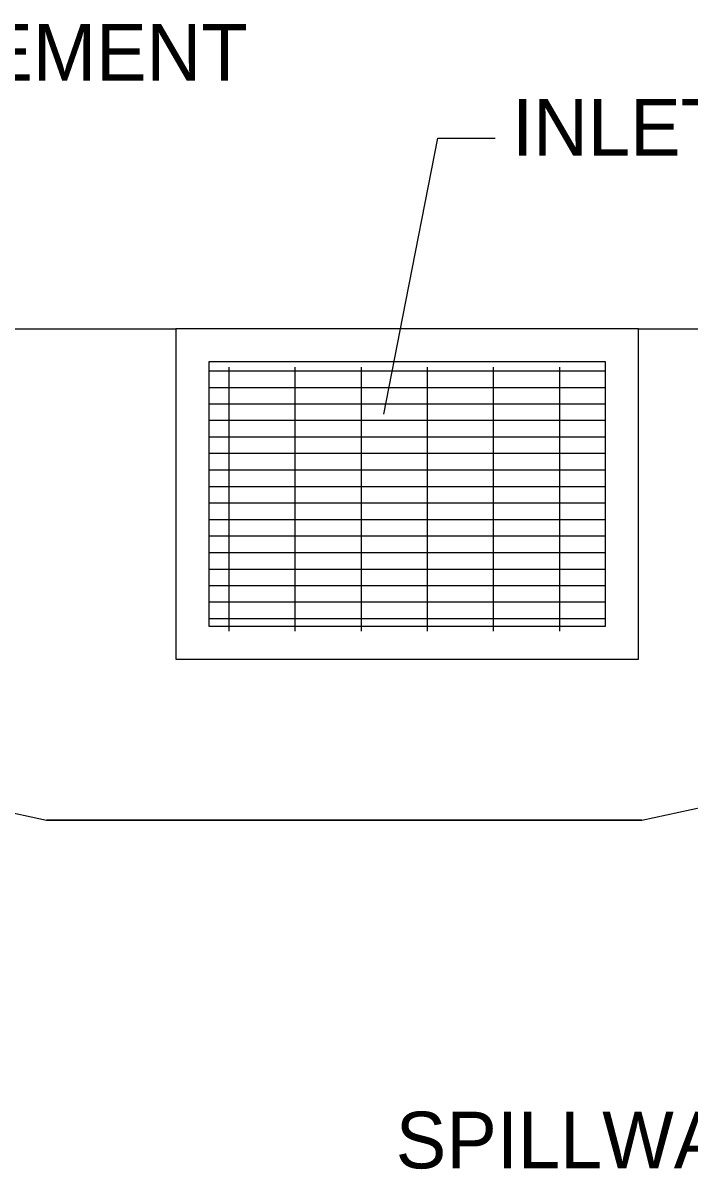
# Model space of a CAD drawing. Extents: x 6707406 to 6714471, y 1868570 to 1872341.
# Drawn here: x 6714138.1 to 6714208.7, y 1870045.9 to 1870168.4 of the extents above; entities that cross this region are included whole.
import ezdxf

# ---------------------------------------------------------------- set-up
doc = ezdxf.new("R2010")
doc.units = 0
doc.layers.add('Control (1)', color=7, linetype='Continuous')
doc.layers.add('Nongeo Data(60)', color=7, linetype='Continuous')

# ---------------------------------------------------------------- blocks, each defined once
blk = doc.blocks.new('SC30')
at = {"layer": 'Control (1)'}
for p, q in [((0.198117, 0.180633), (0.198117, 0.20095)), ((0.2032, 0.180633), (0.2032, 0.20095)), ((0.208283, 0.180633), (0.208283, 0.20095)), ((0.213367, 0.180633), (0.213367, 0.20095)), ((0.218433, 0.180633), (0.218433, 0.20095)), ((0.223517, 0.180633), (0.223517, 0.20095)), ((0.19655, 0.200667), (0.227033, 0.200667)), ((0.19655, 0.199383), (0.227033, 0.199383)), ((0.19655, 0.198117), (0.227033, 0.198117)), ((0.19655, 0.19685), (0.227033, 0.19685)), ((0.19655, 0.195583), (0.227033, 0.195583)), ((0.19655, 0.194317), (0.227033, 0.194317)), ((0.19655, 0.193033), (0.227033, 0.193033)), ((0.19655, 0.191767), (0.227033, 0.191767)), ((0.19655, 0.1905), (0.227033, 0.1905)), ((0.19655, 0.189233), (0.227033, 0.189233)), ((0.19655, 0.187967), (0.227033, 0.187967)), ((0.19655, 0.186683), (0.227033, 0.186683)), ((0.19655, 0.185417), (0.227033, 0.185417)), ((0.19655, 0.18415), (0.227033, 0.18415)), ((0.19655, 0.182883), (0.227033, 0.182883)), ((0.19655, 0.181617), (0.227033, 0.181617))]:
    blk.add_line(p, q, dxfattribs=at)

msp = doc.modelspace()

# ---------------------------------------------------------------- linework, layer by layer
at = {"layer": 'Nongeo Data(60)'}
for p, q in [((6714178.31, 1870137.28), (6714181.99, 1870156.21)), ((6714181.99, 1870156.21), (6714188.07, 1870156.21)), ((6714176.29, 1870126.97), (6714178.31, 1870137.28)), ((6714044.08, 1870136), (6714154.27, 1870136)), ((6714203.25, 1870136), (6714215.59, 1870136)), ((6714110.08, 1870090.5), (6714140.6, 1870083.96)), ((6714203.6, 1870083.96), (6714234.12, 1870090.5)), ((6714203.6, 1870083.96), (6714140.6, 1870083.96)), ((6714140.6, 1870083.96), (6714203.6, 1870083.96))]:
    msp.add_line(p, q, dxfattribs=at)
for points in [[(6714154.27, 1870136), (6714154.27, 1870101), (6714203.25, 1870101), (6714203.25, 1870136)], [(6714157.76, 1870132.51), (6714157.76, 1870104.51), (6714199.76, 1870104.51), (6714199.76, 1870132.51)]]:
    msp.add_lwpolyline(points, close=True, dxfattribs=at)

# ---------------------------------------------------------------- block references
at = {"layer": 'Nongeo Data(60)', "xscale": 1377.952750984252, "yscale": 1377.952750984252}
msp.add_blockref('SC30', (6713886.92, 1869855.06), dxfattribs=at)

# ---------------------------------------------------------------- texts
at = {"layer": 'Nongeo Data(60)'}
for s, p in [('EDGE OF PAVEMENT', (6714079.4, 1870162.3)), ('INLET', (6714189.87, 1870154.34)), ('SPILLWAY, 1-BAG HIGH', (6714177.55, 1870047.06))]:
    msp.add_text(s, height=6, dxfattribs=at).set_placement(p)

doc.saveas('drawing.dxf')
